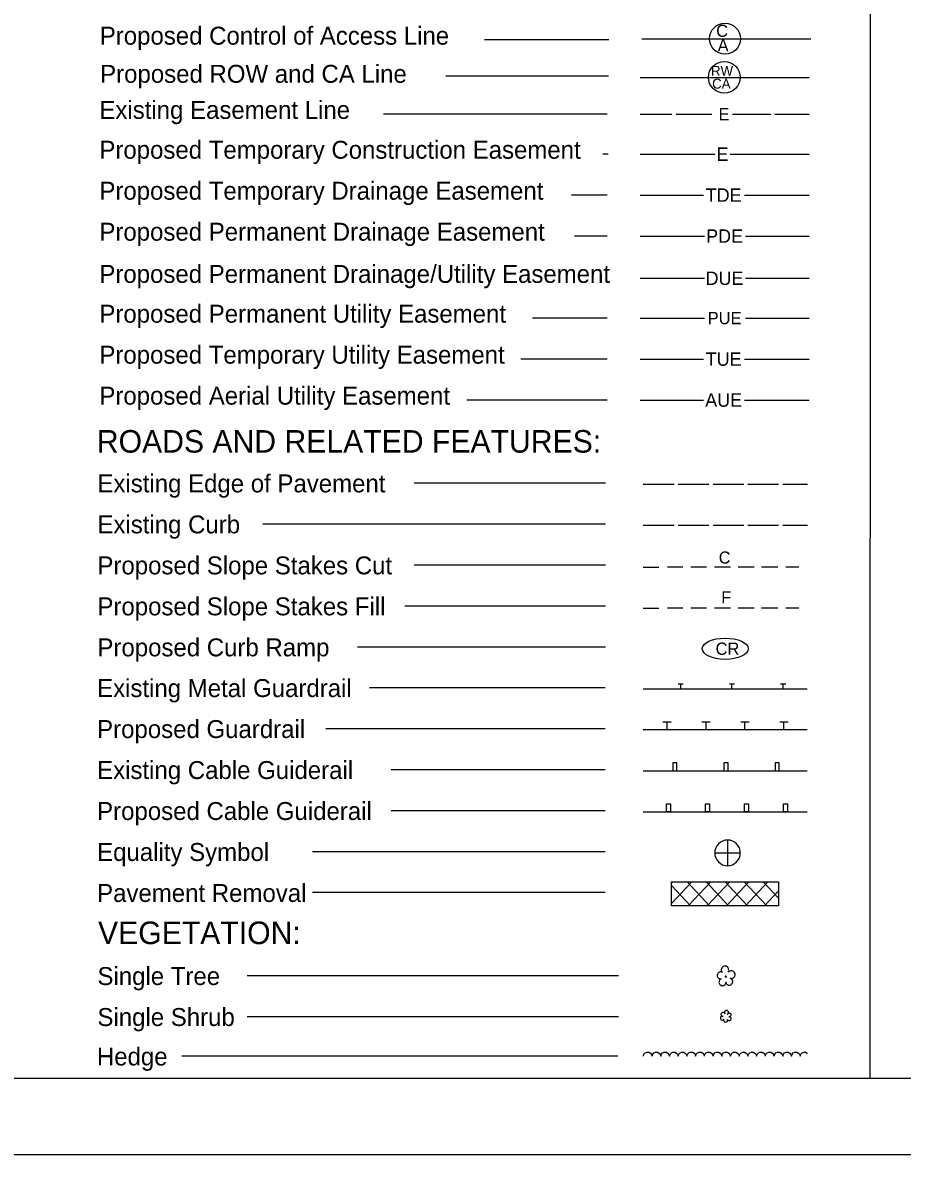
# Model space of a CAD drawing. Extents: x -0.53 to 3.34, y -0.27 to 4.33.
# Drawn here: x 0.939 to 1.661, y 2.495 to 3.424 of the extents above; entities that cross this region are included whole.
import ezdxf

# ---------------------------------------------------------------- set-up
doc = ezdxf.new("R2010")
doc.units = 0
for name, color, linetype in [('P_RDY_Easement_Permanent_Drainage_Utility', 7, 'Continuous'), ('P_RDY_WCC_CELL', 7, 'Continuous'), ('Sheet_Plan', 7, 'Continuous'), ('Sheet_Symbology', 7, 'Continuous'), ('z - Construction', 7, 'Continuous')]:
    doc.layers.add(name, color=color, linetype=linetype)

msp = doc.modelspace()

# ---------------------------------------------------------------- linework, layer by layer
at = {"layer": 'P_RDY_Easement_Permanent_Drainage_Utility'}
for p, q in [((1.44552, 3.21405), (1.49815, 3.21405)), ((1.53178, 3.21405), (1.58424, 3.21405))]:
    msp.add_line(p, q, dxfattribs=at)
at = {"layer": 'P_RDY_WCC_CELL'}
msp.add_ellipse((1.5153, 2.90999), major_axis=(0.01886, 0), ratio=0.462467, dxfattribs=at)
at = {"layer": 'Sheet_Plan'}
msp.add_line((0.2799, 2.55761), (2.98819, 2.55761), dxfattribs=at)
at = {"layer": 'Sheet_Symbology'}
for p, q in [((1.4198, 3.40979), (1.31771, 3.40979)), ((1.44675, 3.41043), (1.58548, 3.41043)), ((1.41963, 3.37994), (1.28618, 3.37994)), ((1.44553, 3.37864), (1.58426, 3.37864)), ((1.41856, 3.34863), (1.23485, 3.34863)), ((1.44552, 3.34863), (1.4716, 3.34863)), ((1.47496, 3.34863), (1.50439, 3.34863)), ((1.52121, 3.34863), (1.55274, 3.34863)), ((1.5561, 3.34863), (1.58424, 3.34863)), ((1.41921, 3.31592), (1.41497, 3.31592)), ((1.44552, 3.31592), (1.44991, 3.31592)), ((1.44991, 3.31592), (1.50666, 3.31592)), ((1.51927, 3.31592), (1.57603, 3.31592)), ((1.57603, 3.31592), (1.58424, 3.31592)), ((1.41856, 3.28229), (1.38914, 3.28229)), ((1.44552, 3.28229), (1.45115, 3.28229)), ((1.45115, 3.28229), (1.49739, 3.28229)), ((1.53102, 3.28229), (1.57727, 3.28229)), ((1.57727, 3.28229), (1.58424, 3.28229)), ((1.41856, 3.24865), (1.39164, 3.24865)), ((1.44552, 3.24865), (1.45191, 3.24865)), ((1.45191, 3.24865), (1.49815, 3.24865)), ((1.53178, 3.24865), (1.57802, 3.24865)), ((1.57802, 3.24865), (1.58424, 3.24865)), ((1.41856, 3.18138), (1.35733, 3.18138)), ((1.44552, 3.18138), (1.45197, 3.18138)), ((1.45197, 3.18138), (1.49821, 3.18138)), ((1.53184, 3.18138), (1.57809, 3.18138)), ((1.57809, 3.18138), (1.58424, 3.18138)), ((1.41856, 3.14775), (1.3477, 3.14775)), ((1.44552, 3.14775), (1.45115, 3.14775)), ((1.45115, 3.14775), (1.49739, 3.14775)), ((1.53102, 3.14775), (1.57727, 3.14775)), ((1.57727, 3.14775), (1.58424, 3.14775)), ((1.41856, 3.11411), (1.30345, 3.11411)), ((1.44552, 3.11411), (1.45115, 3.11411)), ((1.45115, 3.11411), (1.49739, 3.11411)), ((1.53102, 3.11411), (1.57727, 3.11411)), ((1.57727, 3.11411), (1.58424, 3.11411)), ((1.41694, 3.04597), (1.26016, 3.04597)), ((1.4481, 3.045), (1.47333, 3.045)), ((1.47669, 3.045), (1.50191, 3.045)), ((1.50528, 3.045), (1.5305, 3.045)), ((1.53386, 3.045), (1.55909, 3.045)), ((1.56245, 3.045), (1.58263, 3.045)), ((1.41694, 3.01234), (1.13587, 3.01234)), ((1.4481, 3.01137), (1.47333, 3.01137)), ((1.47669, 3.01137), (1.50191, 3.01137)), ((1.50528, 3.01137), (1.5305, 3.01137)), ((1.53386, 3.01137), (1.55909, 3.01137)), ((1.56245, 3.01137), (1.58263, 3.01137)), ((1.41694, 2.9787), (1.26024, 2.9787)), ((1.4481, 2.97694), (1.46088, 2.97694)), ((1.48056, 2.97694), (1.46786, 2.97694)), ((1.49989, 2.97694), (1.48711, 2.97694)), ((1.51965, 2.97694), (1.50654, 2.97694)), ((1.53891, 2.97694), (1.52587, 2.97694)), ((1.55833, 2.97694), (1.54513, 2.97694)), ((1.57565, 2.97694), (1.56489, 2.97694)), ((1.41694, 2.94507), (1.25259, 2.94507)), ((1.4481, 2.94331), (1.46088, 2.94331)), ((1.48056, 2.94331), (1.46786, 2.94331)), ((1.49989, 2.94331), (1.48711, 2.94331)), ((1.51965, 2.94331), (1.50654, 2.94331)), ((1.53891, 2.94331), (1.52587, 2.94331)), ((1.55833, 2.94331), (1.54513, 2.94331)), ((1.57565, 2.94331), (1.56489, 2.94331)), ((1.41694, 2.91144), (1.2136, 2.91144)), ((1.47666, 2.88125), (1.48086, 2.88125)), ((1.47876, 2.87705), (1.47876, 2.88125)), ((1.5187, 2.88125), (1.5229, 2.88125)), ((1.5208, 2.87705), (1.5208, 2.88125)), ((1.56074, 2.88125), (1.56494, 2.88125)), ((1.56284, 2.87705), (1.56284, 2.88125)), ((1.41668, 2.87801), (1.22357, 2.87801)), ((1.44784, 2.87705), (1.58236, 2.87705)), ((1.41668, 2.84438), (1.18759, 2.84438)), ((1.58236, 2.84341), (1.44784, 2.84341)), ((1.46419, 2.85006), (1.47092, 2.85006)), ((1.46756, 2.84341), (1.46756, 2.85006)), ((1.49614, 2.85006), (1.50287, 2.85006)), ((1.49951, 2.84341), (1.49951, 2.85006)), ((1.52809, 2.85006), (1.53482, 2.85006)), ((1.53146, 2.84341), (1.53146, 2.85006)), ((1.56004, 2.85006), (1.56677, 2.85006)), ((1.5634, 2.84341), (1.5634, 2.85006)), ((1.41668, 2.81075), (1.24129, 2.81075)), ((1.44784, 2.80978), (1.58236, 2.80978)), ((1.41668, 2.77712), (1.24129, 2.77712)), ((1.44784, 2.77615), (1.58236, 2.77615)), ((1.51716, 2.75301), (1.51716, 2.7425)), ((1.41668, 2.74349), (1.17685, 2.74349)), ((1.50665, 2.7425), (1.51716, 2.7425)), ((1.51716, 2.7425), (1.51716, 2.73199)), ((1.51716, 2.7425), (1.52767, 2.7425)), ((1.4713, 2.71875), (1.55891, 2.71875)), ((1.4713, 2.69907), (1.4713, 2.71875)), ((1.4713, 2.71774), (1.47222, 2.71875)), ((1.4713, 2.70101), (1.48786, 2.71875)), ((1.48685, 2.69907), (1.4713, 2.71572)), ((1.50249, 2.69907), (1.48399, 2.71875)), ((1.485, 2.69907), (1.5035, 2.71875)), ((1.51804, 2.69907), (1.49963, 2.71875)), ((1.50056, 2.69907), (1.51914, 2.71875)), ((1.53368, 2.69907), (1.51519, 2.71875)), ((1.51619, 2.69907), (1.53469, 2.71875)), ((1.54932, 2.69907), (1.53074, 2.71875)), ((1.53183, 2.69907), (1.55025, 2.71875)), ((1.55891, 2.70538), (1.54638, 2.71875)), ((1.55891, 2.71875), (1.55891, 2.69907)), ((1.41668, 2.70986), (1.17685, 2.70986)), ((1.54739, 2.69907), (1.55891, 2.71135)), ((1.55891, 2.69907), (1.4713, 2.69907)), ((1.42774, 2.64168), (1.12317, 2.64168)), ((1.42774, 2.60805), (1.12317, 2.60805)), ((1.42729, 2.57566), (1.06965, 2.57566)), ((1.44813, 2.57566), (1.44864, 2.57726)), ((1.44864, 2.57726), (1.44965, 2.57835)), ((1.44965, 2.57835), (1.45099, 2.57911)), ((1.45099, 2.57911), (1.45259, 2.57911)), ((1.45259, 2.57911), (1.45393, 2.57827)), ((1.45393, 2.57827), (1.45486, 2.57718)), ((1.45486, 2.57718), (1.4552, 2.57575)), ((1.45528, 2.57566), (1.45578, 2.57726)), ((1.45578, 2.57726), (1.45679, 2.57835)), ((1.45679, 2.57835), (1.45814, 2.57911)), ((1.45814, 2.57911), (1.45974, 2.57911)), ((1.45974, 2.57911), (1.46108, 2.57827)), ((1.46108, 2.57827), (1.46201, 2.57718)), ((1.46201, 2.57718), (1.46234, 2.57575)), ((1.46243, 2.57566), (1.46293, 2.57726)), ((1.46293, 2.57726), (1.46394, 2.57835)), ((1.46394, 2.57835), (1.46529, 2.57911)), ((1.46529, 2.57911), (1.46688, 2.57911)), ((1.46688, 2.57911), (1.46823, 2.57827)), ((1.46823, 2.57827), (1.46915, 2.57718)), ((1.46915, 2.57718), (1.46949, 2.57575)), ((1.46957, 2.57566), (1.47008, 2.57726)), ((1.47008, 2.57726), (1.47109, 2.57835)), ((1.47109, 2.57835), (1.47243, 2.57911)), ((1.47243, 2.57911), (1.47403, 2.57911)), ((1.47403, 2.57911), (1.47537, 2.57827)), ((1.47537, 2.57827), (1.4763, 2.57718)), ((1.4763, 2.57718), (1.47664, 2.57575)), ((1.47672, 2.57566), (1.47722, 2.57726)), ((1.47722, 2.57726), (1.47823, 2.57835)), ((1.47823, 2.57835), (1.47958, 2.57911)), ((1.47958, 2.57911), (1.48118, 2.57911)), ((1.48118, 2.57911), (1.48252, 2.57827)), ((1.48252, 2.57827), (1.48345, 2.57718)), ((1.48345, 2.57718), (1.48378, 2.57575)), ((1.48387, 2.57566), (1.48437, 2.57726)), ((1.48437, 2.57726), (1.48538, 2.57835)), ((1.48538, 2.57835), (1.48673, 2.57911)), ((1.48673, 2.57911), (1.48832, 2.57911)), ((1.48832, 2.57911), (1.48967, 2.57827)), ((1.48967, 2.57827), (1.49059, 2.57718)), ((1.49059, 2.57718), (1.49093, 2.57575)), ((1.49101, 2.57566), (1.49152, 2.57726)), ((1.49152, 2.57726), (1.49253, 2.57835)), ((1.49253, 2.57835), (1.49387, 2.57911)), ((1.49387, 2.57911), (1.49547, 2.57911)), ((1.49547, 2.57911), (1.49681, 2.57827)), ((1.49681, 2.57827), (1.49774, 2.57718)), ((1.49774, 2.57718), (1.49808, 2.57575)), ((1.49816, 2.57566), (1.49866, 2.57726)), ((1.49866, 2.57726), (1.49967, 2.57835)), ((1.49967, 2.57835), (1.50102, 2.57911)), ((1.50102, 2.57911), (1.50262, 2.57911)), ((1.50262, 2.57911), (1.50396, 2.57827)), ((1.50396, 2.57827), (1.50489, 2.57718)), ((1.50489, 2.57718), (1.50522, 2.57575)), ((1.50531, 2.57566), (1.50581, 2.57726)), ((1.50581, 2.57726), (1.50682, 2.57835)), ((1.50682, 2.57835), (1.50817, 2.57911)), ((1.50817, 2.57911), (1.50976, 2.57911)), ((1.50976, 2.57911), (1.51111, 2.57827)), ((1.51111, 2.57827), (1.51203, 2.57718)), ((1.51203, 2.57718), (1.51237, 2.57575)), ((1.51245, 2.57566), (1.51296, 2.57726)), ((1.51296, 2.57726), (1.51397, 2.57835)), ((1.51397, 2.57835), (1.51531, 2.57911)), ((1.51531, 2.57911), (1.51691, 2.57911)), ((1.51691, 2.57911), (1.51825, 2.57827)), ((1.51825, 2.57827), (1.51918, 2.57718)), ((1.51918, 2.57718), (1.51952, 2.57575)), ((1.5196, 2.57566), (1.5201, 2.57726)), ((1.5201, 2.57726), (1.52111, 2.57835)), ((1.52111, 2.57835), (1.52246, 2.57911)), ((1.52246, 2.57911), (1.52406, 2.57911)), ((1.52406, 2.57911), (1.5254, 2.57827)), ((1.5254, 2.57827), (1.52633, 2.57718)), ((1.52633, 2.57718), (1.52666, 2.57575)), ((1.52675, 2.57566), (1.52725, 2.57726)), ((1.52725, 2.57726), (1.52826, 2.57835)), ((1.52826, 2.57835), (1.5296, 2.57911)), ((1.5296, 2.57911), (1.5312, 2.57911)), ((1.5312, 2.57911), (1.53255, 2.57827)), ((1.53255, 2.57827), (1.53347, 2.57718)), ((1.53347, 2.57718), (1.53381, 2.57575)), ((1.53389, 2.57566), (1.5344, 2.57726)), ((1.5344, 2.57726), (1.53541, 2.57835)), ((1.53541, 2.57835), (1.53675, 2.57911)), ((1.53675, 2.57911), (1.53835, 2.57911)), ((1.53835, 2.57911), (1.53969, 2.57827)), ((1.53969, 2.57827), (1.54062, 2.57718)), ((1.54062, 2.57718), (1.54096, 2.57575)), ((1.54104, 2.57566), (1.54154, 2.57726)), ((1.54154, 2.57726), (1.54255, 2.57835)), ((1.54255, 2.57835), (1.5439, 2.57911)), ((1.5439, 2.57911), (1.5455, 2.57911)), ((1.5455, 2.57911), (1.54684, 2.57827)), ((1.54684, 2.57827), (1.54777, 2.57718)), ((1.54777, 2.57718), (1.5481, 2.57575)), ((1.54819, 2.57566), (1.54869, 2.57726)), ((1.54869, 2.57726), (1.5497, 2.57835)), ((1.5497, 2.57835), (1.55104, 2.57911)), ((1.55104, 2.57911), (1.55264, 2.57911)), ((1.55264, 2.57911), (1.55399, 2.57827)), ((1.55399, 2.57827), (1.55491, 2.57718)), ((1.55491, 2.57718), (1.55525, 2.57575)), ((1.55533, 2.57566), (1.55584, 2.57726)), ((1.55584, 2.57726), (1.55685, 2.57835)), ((1.55685, 2.57835), (1.55819, 2.57911)), ((1.55819, 2.57911), (1.55979, 2.57911)), ((1.55979, 2.57911), (1.56113, 2.57827)), ((1.56113, 2.57827), (1.56206, 2.57718)), ((1.56206, 2.57718), (1.5624, 2.57575)), ((1.56248, 2.57566), (1.56298, 2.57726)), ((1.56298, 2.57726), (1.56399, 2.57835)), ((1.56399, 2.57835), (1.56534, 2.57911)), ((1.56534, 2.57911), (1.56694, 2.57911)), ((1.56694, 2.57911), (1.56828, 2.57827)), ((1.56828, 2.57827), (1.56921, 2.57718)), ((1.56921, 2.57718), (1.56954, 2.57575)), ((1.56963, 2.57566), (1.57013, 2.57726)), ((1.57013, 2.57726), (1.57114, 2.57835)), ((1.57114, 2.57835), (1.57248, 2.57911)), ((1.57248, 2.57911), (1.57408, 2.57911)), ((1.57408, 2.57911), (1.57543, 2.57827)), ((1.57543, 2.57827), (1.57635, 2.57718)), ((1.57635, 2.57718), (1.57669, 2.57575)), ((1.57677, 2.57566), (1.57728, 2.57726)), ((1.57728, 2.57726), (1.57829, 2.57835)), ((1.57829, 2.57835), (1.57963, 2.57911)), ((1.57963, 2.57911), (1.58123, 2.57911)), ((1.58123, 2.57911), (1.58257, 2.57827)), ((1.58257, 2.57827), (1.58266, 2.57819))]:
    msp.add_line(p, q, dxfattribs=at)
for points in [[(1.47218, 2.80978), (1.47554, 2.80978), (1.47554, 2.81651), (1.47218, 2.81651)], [(1.51422, 2.80978), (1.51758, 2.80978), (1.51758, 2.81651), (1.51422, 2.81651)], [(1.55626, 2.80978), (1.55962, 2.80978), (1.55962, 2.81651), (1.55626, 2.81651)], [(1.46711, 2.78288), (1.47048, 2.78288), (1.47048, 2.77615), (1.46711, 2.77615)], [(1.49906, 2.78288), (1.50243, 2.78288), (1.50243, 2.77615), (1.49906, 2.77615)], [(1.53101, 2.78288), (1.53438, 2.78288), (1.53438, 2.77615), (1.53101, 2.77615)], [(1.56296, 2.78288), (1.56633, 2.78288), (1.56633, 2.77615), (1.56296, 2.77615)]]:
    msp.add_lwpolyline(points, close=True, dxfattribs=at)
for points in [[(1.51777, 2.64519), (1.51803, 2.64578), (1.51816, 2.64638), (1.5181, 2.64704), (1.51796, 2.64764), (1.51763, 2.64823), (1.5173, 2.6487), (1.51677, 2.64916), (1.51624, 2.64942), (1.51558, 2.64962), (1.51499, 2.64962), (1.51432, 2.64956), (1.51373, 2.64936), (1.5132, 2.64903), (1.51273, 2.64856), (1.5124, 2.64804), (1.51214, 2.64744), (1.51207, 2.64684), (1.51207, 2.64618), (1.5122, 2.64559), (1.51247, 2.64499), (1.51287, 2.64446), (1.51234, 2.64473), (1.51174, 2.64486), (1.51115, 2.64479), (1.51055, 2.64466), (1.51002, 2.64439), (1.50949, 2.644), (1.50916, 2.64353), (1.50883, 2.643), (1.5087, 2.64247), (1.50863, 2.64181), (1.5087, 2.64122), (1.50896, 2.64069), (1.50929, 2.64016), (1.50969, 2.63976), (1.51022, 2.63943), (1.51075, 2.63916), (1.51134, 2.6391), (1.51194, 2.6391), (1.51141, 2.63883), (1.51095, 2.63844), (1.51062, 2.63797), (1.51035, 2.63738), (1.51022, 2.63678), (1.51015, 2.63618), (1.51029, 2.63559), (1.51055, 2.63506), (1.51088, 2.63453), (1.51128, 2.63413), (1.51181, 2.6338), (1.5124, 2.6336), (1.513, 2.63354), (1.51359, 2.6336), (1.51419, 2.63374), (1.51472, 2.63407), (1.51518, 2.63446), (1.51552, 2.63493), (1.51578, 2.63546), (1.51591, 2.63605)], [(1.51591, 2.64148), (1.51565, 2.64148), (1.51538, 2.64141), (1.51525, 2.64122), (1.51518, 2.64095), (1.51525, 2.64069), (1.51545, 2.64049), (1.51571, 2.64049), (1.51598, 2.64055), (1.51618, 2.64075), (1.51624, 2.64102), (1.51611, 2.64128), (1.51591, 2.64148)], [(1.51571, 2.63678), (1.51578, 2.63612), (1.51598, 2.63552), (1.51631, 2.63499), (1.51677, 2.63453), (1.5173, 2.6342), (1.5179, 2.634), (1.51856, 2.63393), (1.51916, 2.634), (1.51975, 2.6342), (1.52028, 2.63453), (1.52074, 2.63493), (1.52114, 2.63546), (1.52134, 2.63605), (1.52147, 2.63665), (1.52141, 2.63731), (1.52127, 2.63791), (1.52094, 2.6385), (1.52055, 2.63897), (1.52002, 2.6393), (1.51942, 2.63956), (1.52008, 2.6395), (1.52074, 2.6395), (1.52134, 2.63969), (1.52194, 2.63996), (1.52247, 2.64036), (1.52286, 2.64088), (1.52319, 2.64148), (1.52333, 2.64208), (1.52339, 2.64274), (1.52326, 2.6434), (1.52306, 2.644), (1.52267, 2.64453), (1.5222, 2.64499), (1.52167, 2.64532), (1.52101, 2.64559), (1.52042, 2.64565), (1.51975, 2.64565), (1.51909, 2.64545), (1.51856, 2.64512), (1.51803, 2.64473)], [(1.51492, 2.6105), (1.51472, 2.6109), (1.51432, 2.61123), (1.51393, 2.61149), (1.51346, 2.61156), (1.513, 2.61149), (1.51254, 2.61136), (1.51214, 2.61103), (1.51187, 2.61063), (1.51174, 2.61017), (1.51174, 2.6097), (1.51187, 2.60924), (1.51214, 2.60884), (1.51254, 2.60851), (1.513, 2.60831), (1.51346, 2.60831), (1.513, 2.60838), (1.51254, 2.60838), (1.51214, 2.60825), (1.51174, 2.60798), (1.51148, 2.60765), (1.51134, 2.60725), (1.51128, 2.60679), (1.51134, 2.60633), (1.51154, 2.60593), (1.51187, 2.6056), (1.51227, 2.6054), (1.51267, 2.60527), (1.51313, 2.60533), (1.51353, 2.60547), (1.51393, 2.60573), (1.51419, 2.60606), (1.51399, 2.6056), (1.51393, 2.60514), (1.51406, 2.60467), (1.51426, 2.60428), (1.51459, 2.60388), (1.51499, 2.60368), (1.51545, 2.60355), (1.51591, 2.60361), (1.51638, 2.60375), (1.51677, 2.60401), (1.51704, 2.60441), (1.51724, 2.60487), (1.51724, 2.60533), (1.51717, 2.6058), (1.51737, 2.60547), (1.51777, 2.60514), (1.51816, 2.605), (1.51863, 2.60494), (1.51909, 2.605), (1.51949, 2.6052), (1.51982, 2.60553), (1.52002, 2.60593), (1.52008, 2.60639), (1.52008, 2.60686), (1.51989, 2.60725), (1.51962, 2.60758), (1.51929, 2.60785), (1.51883, 2.60805), (1.51836, 2.60805), (1.51883, 2.60805), (1.51929, 2.60818), (1.51962, 2.60844), (1.51995, 2.60884), (1.52008, 2.60924), (1.52008, 2.6097), (1.52002, 2.61017), (1.51975, 2.61056), (1.51942, 2.61083), (1.51896, 2.61103), (1.51849, 2.61109), (1.5181, 2.61096), (1.51763, 2.61076), (1.51737, 2.61043), (1.51717, 2.61003)], [(1.51697, 2.61003), (1.51737, 2.61023), (1.5177, 2.61063), (1.5179, 2.61103), (1.51796, 2.61149), (1.51796, 2.61195), (1.51777, 2.61242), (1.5175, 2.61275), (1.51717, 2.61308), (1.51671, 2.61321), (1.51624, 2.61328), (1.51578, 2.61321), (1.51538, 2.61301), (1.51499, 2.61268), (1.51479, 2.61228), (1.51465, 2.61182), (1.51465, 2.61136), (1.51472, 2.6109), (1.51499, 2.6105)]]:
    msp.add_lwpolyline(points, dxfattribs=at)
for centre, radius in [((1.5151, 3.41061), 0.01275), ((1.51446, 3.37889), 0.01298)]:
    msp.add_circle(centre, radius, dxfattribs=at)
for start, end in [(89.99439, 179.99893), (359.99439, 89.99893), (179.99439, 269.99892), (269.99439, 359.99893)]:
    msp.add_arc((1.51716, 2.7425), 0.01051, start, end, dxfattribs=at)
at = {"layer": 'z - Construction'}
for p, q in [((1.63406, 4.26594), (1.63402, 2.55761)), ((0.2174, 2.49511), (3.05073, 2.49511))]:
    msp.add_line(p, q, dxfattribs=at)

# ---------------------------------------------------------------- texts
at = {"layer": 'P_RDY_Easement_Permanent_Drainage_Utility'}
msp.add_text('DUE', height=0.011014, dxfattribs=at).set_placement((1.49916, 3.2085))
at = {"layer": 'P_RDY_WCC_CELL'}
msp.add_text('CR', height=0.010089, dxfattribs=at).set_placement((1.50738, 2.90502))
at = {"layer": 'Sheet_Symbology'}
for s, height, p in [('Proposed Control of Access Line', 0.0147137, (1.00227, 3.40571)), ('C', 0.00999, (1.50789, 3.41211)), ('A', 0.00999, (1.50908, 3.40011)), ('Proposed ROW and CA Line', 0.0147137, (1.00256, 3.37442)), ('RW', 0.008136, (1.50361, 3.38018)), ('CA', 0.008136, (1.50455, 3.36961)), ('Existing Easement Line', 0.0147137, (1.00195, 3.34483)), ('E', 0.01009, (1.50977, 3.34359)), ('Proposed Temporary Construction Easement', 0.0147137, (1.00195, 3.31211)), ('E', 0.01101, (1.5081, 3.31037)), ('Proposed Temporary Drainage Easement', 0.0147137, (1.00195, 3.27848)), ('TDE', 0.011014, (1.49926, 3.27674)), ('Proposed Permanent Drainage Easement', 0.0147137, (1.00195, 3.24485)), ('PDE', 0.011014, (1.49958, 3.24311)), ('Proposed Permanent Drainage/Utility Easement', 0.0147137, (1.00195, 3.21024)), ('Proposed Permanent Utility Easement', 0.0147137, (1.00195, 3.17757)), ('PUE', 0.010089, (1.50092, 3.17633)), ('Proposed Temporary Utility Easement', 0.0147137, (1.00195, 3.14394)), ('TUE', 0.011014, (1.49926, 3.1422)), ('Proposed Aerial Utility Easement', 0.0147137, (1.00195, 3.11031)), ('AUE', 0.011014, (1.49883, 3.10857)), ('ROADS AND RELATED FEATURES:', 0.0184972, (0.99983, 3.07093)), ('Existing Edge of Pavement', 0.0147137, (1.00034, 3.03832)), ('Existing Curb', 0.0147137, (1.00034, 3.00468)), ('Proposed Slope Stakes Cut', 0.0147137, (1.00034, 2.97105)), ('C', 0.00997, (1.50998, 2.97986)), ('F', 0.00997, (1.512, 2.94728)), ('Proposed Slope Stakes Fill', 0.0147137, (1.00034, 2.93742)), ('Proposed Curb Ramp', 0.0147137, (1.00034, 2.90379)), ('Existing Metal Guardrail', 0.0147137, (1.00007, 2.87036)), ('Proposed Guardrail', 0.0147137, (1.00009, 2.83675)), ('Existing Cable Guiderail', 0.0147137, (1.00009, 2.80312)), ('Proposed Cable Guiderail', 0.0147137, (1.00009, 2.76949)), ('Equality Symbol', 0.0147137, (1.00009, 2.73586)), ('Pavement Removal', 0.0147137, (1.00009, 2.70223)), ('VEGETATION:', 0.0184972, (1.00082, 2.66766)), ('Single Tree', 0.0147137, (1.00035, 2.63407)), ('Single Shrub', 0.0147137, (1.00035, 2.60044)), ('Hedge', 0.014714, (0.9999, 2.56805))]:
    msp.add_text(s, height=height, dxfattribs=at).set_placement(p)

doc.saveas('drawing.dxf')
